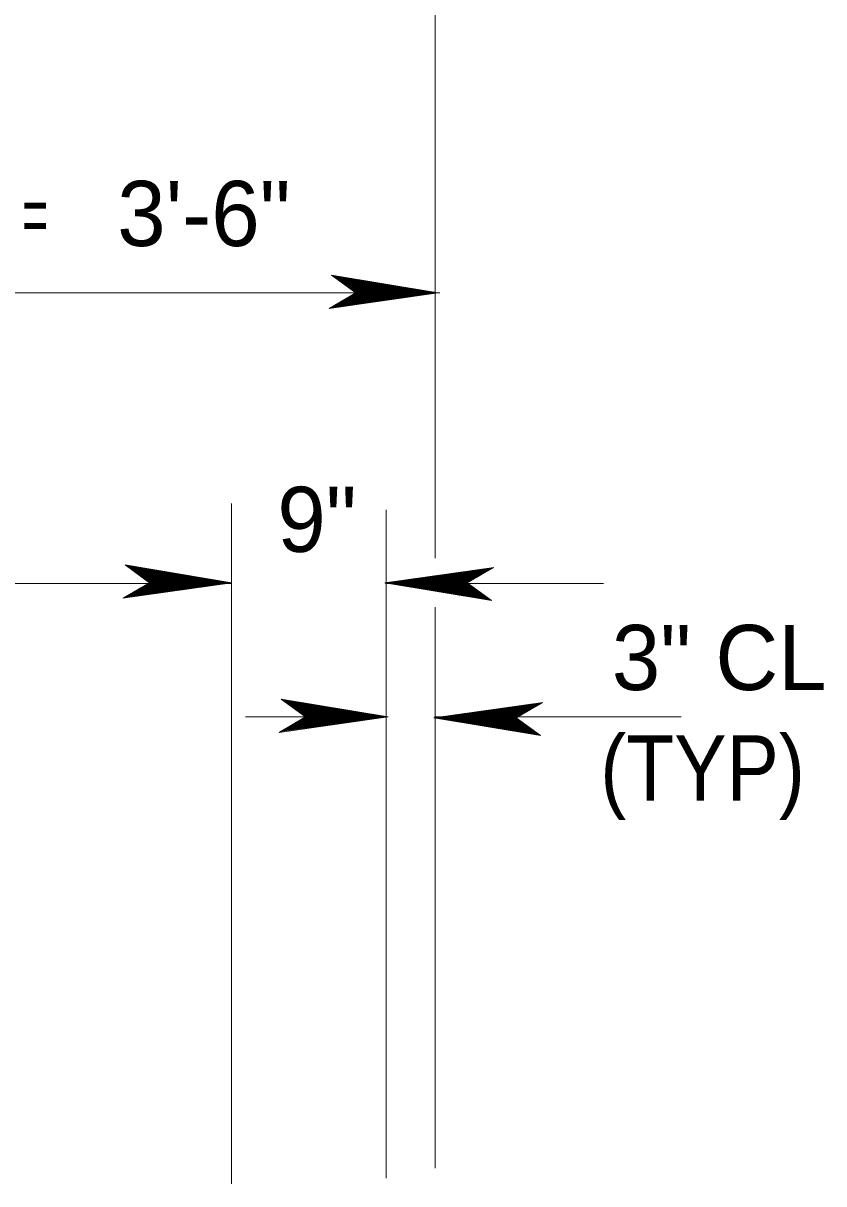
# Model space of a CAD drawing. Extents: x 144 to 252, y 360 to 425.
# Drawn here: x 196.74 to 200.77, y 372.84 to 378.68 of the extents above; entities that cross this region are included whole.
import ezdxf
from ezdxf.enums import TextEntityAlignment as Align

# ---------------------------------------------------------------- set-up
doc = ezdxf.new("R2010")
doc.units = 0
doc.header["$LTSCALE"] = 0.13
for name, color, linetype, lineweight in [('1', 7, 'Continuous', 40), ('16', 7, 'Continuous', 13), ('3', 7, 'Continuous', 13)]:
    doc.layers.add(name, color=color, linetype=linetype, lineweight=lineweight)

msp = doc.modelspace()

# ---------------------------------------------------------------- linework, layer by layer
at = {"layer": '3'}
for p, q in [((198.8108, 375.9887), (198.8108, 379.4017)), ((198.8108, 376.0572), (198.8108, 378.3742)), ((198.8265, 377.3248), (198.2888, 377.4141)), ((198.2888, 377.4141), (198.4113, 377.325)), ((198.8121, 377.3255), (198.2921, 377.4117)), ((198.8012, 377.3255), (198.2953, 377.4094)), ((198.7868, 377.3255), (198.2996, 377.4062)), ((198.7741, 377.3255), (198.3033, 377.4036)), ((198.7627, 377.3255), (198.3067, 377.4012)), ((198.7483, 377.3255), (198.3109, 377.398)), ((198.7356, 377.3255), (198.3147, 377.3952)), ((198.7218, 377.3255), (198.3187, 377.3923)), ((198.708, 377.3255), (198.3228, 377.3893)), ((198.6947, 377.3255), (198.3268, 377.3865)), ((198.6808, 377.3255), (198.3308, 377.3835)), ((198.6683, 377.3255), (198.3346, 377.3808)), ((198.6568, 377.3255), (198.338, 377.3783)), ((198.6412, 377.3255), (198.3426, 377.375)), ((198.6273, 377.3255), (198.3467, 377.372)), ((198.6093, 377.326), (198.3509, 377.3689)), ((198.5954, 377.326), (198.3551, 377.3659)), ((198.5822, 377.326), (198.3589, 377.3631)), ((198.5732, 377.3255), (198.3627, 377.3603)), ((198.5612, 377.3255), (198.3662, 377.3578)), ((198.5473, 377.3255), (198.3703, 377.3547)), ((198.5317, 377.3255), (198.375, 377.3515)), ((198.5191, 377.3255), (198.3787, 377.3487)), ((198.5058, 377.3255), (198.3826, 377.3459)), ((198.4938, 377.3255), (198.3862, 377.3433)), ((198.4793, 377.3255), (198.3904, 377.3402)), ((198.4655, 377.3255), (198.3946, 377.3372)), ((198.4528, 377.3255), (198.3982, 377.3345)), ((198.4396, 377.3255), (198.4022, 377.3317)), ((198.4282, 377.3255), (198.4056, 377.3293)), ((198.8346, 377.3247), (195.3467, 377.3247)), ((198.4113, 377.325), (198.2777, 377.2471)), ((198.2777, 377.2471), (198.8265, 377.3248)), ((198.2837, 377.2506), (198.8121, 377.3255)), ((198.2873, 377.2526), (198.8012, 377.3255)), ((198.2918, 377.2552), (198.7868, 377.3255)), ((198.2959, 377.2577), (198.7741, 377.3255)), ((198.2959, 377.2577), (198.7741, 377.3255)), ((198.2996, 377.2598), (198.7627, 377.3255)), ((198.3042, 377.2625), (198.7483, 377.3255)), ((198.3082, 377.2649), (198.7356, 377.3255)), ((198.3127, 377.2674), (198.7218, 377.3255)), ((198.3171, 377.27), (198.708, 377.3255)), ((198.3213, 377.2725), (198.6947, 377.3255)), ((198.3258, 377.2752), (198.6808, 377.3255)), ((198.3298, 377.2774), (198.6683, 377.3255)), ((198.3336, 377.2797), (198.6568, 377.3255)), ((198.3386, 377.2825), (198.6412, 377.3255)), ((198.343, 377.2852), (198.6273, 377.3255)), ((198.347, 377.2874), (198.6077, 377.3244)), ((198.3502, 377.2893), (198.6093, 377.326)), ((198.3546, 377.2919), (198.5954, 377.326)), ((198.3588, 377.2944), (198.5822, 377.326)), ((198.3603, 377.2953), (198.5732, 377.3255)), ((198.3642, 377.2975), (198.5612, 377.3255)), ((198.3687, 377.3002), (198.5473, 377.3255)), ((198.3737, 377.303), (198.5317, 377.3255)), ((198.3777, 377.3054), (198.5191, 377.3255)), ((198.382, 377.3079), (198.5058, 377.3255)), ((198.3858, 377.3102), (198.4938, 377.3255)), ((198.3905, 377.3128), (198.4793, 377.3255)), ((198.3949, 377.3154), (198.4655, 377.3255)), ((198.399, 377.3177), (198.4528, 377.3255)), ((198.4042, 377.3208), (198.4293, 377.3244)), ((198.4069, 377.3224), (198.4282, 377.3255)), ((198.418, 377.3255), (198.4086, 377.327)), ((198.4111, 377.3248), (198.8265, 377.3248)), ((197.7853, 372.8387), (197.7853, 376.265)), ((198.5633, 372.8667), (198.5633, 376.2329)), ((197.786, 375.8657), (197.2483, 375.955)), ((197.2483, 375.955), (197.3708, 375.8659)), ((197.7716, 375.8664), (197.2516, 375.9527)), ((197.7608, 375.8664), (197.2548, 375.9503)), ((197.7463, 375.8664), (197.2591, 375.9472)), ((197.7336, 375.8664), (197.2628, 375.9445)), ((197.7223, 375.8664), (197.2662, 375.9421)), ((197.7078, 375.8664), (197.2704, 375.9389)), ((197.6951, 375.8664), (197.2742, 375.9362)), ((197.6813, 375.8664), (197.2782, 375.9332)), ((197.6675, 375.8664), (197.2823, 375.9303)), ((197.6542, 375.8664), (197.2862, 375.9274)), ((199.1062, 375.9427), (198.5574, 375.8649)), ((199.1002, 375.9392), (198.5718, 375.8642)), ((199.0967, 375.9372), (198.5827, 375.8642)), ((199.0921, 375.9345), (198.5971, 375.8642)), ((199.088, 375.9321), (198.6098, 375.8642)), ((199.088, 375.9321), (198.6098, 375.8642)), ((199.0843, 375.9299), (198.6212, 375.8642)), ((199.0797, 375.9273), (198.6356, 375.8642)), ((199.0757, 375.9248), (198.6483, 375.8642)), ((198.9726, 375.8648), (199.1062, 375.9427)), ((197.2432, 375.7915), (197.7716, 375.8664)), ((197.2467, 375.7935), (197.7608, 375.8664)), ((197.2513, 375.7962), (197.7463, 375.8664)), ((197.2554, 375.7986), (197.7336, 375.8664)), ((197.2554, 375.7986), (197.7336, 375.8664)), ((197.2591, 375.8007), (197.7223, 375.8664)), ((197.2637, 375.8034), (197.7078, 375.8664)), ((197.2678, 375.8058), (197.6951, 375.8664)), ((197.2722, 375.8083), (197.6813, 375.8664)), ((197.2766, 375.8109), (197.6675, 375.8664)), ((197.2808, 375.8134), (197.6542, 375.8664)), ((197.2853, 375.8161), (197.6403, 375.8664)), ((197.2893, 375.8183), (197.6277, 375.8664)), ((197.6403, 375.8664), (197.2903, 375.9244)), ((197.2931, 375.8206), (197.6163, 375.8664)), ((197.6277, 375.8664), (197.2941, 375.9217)), ((197.6163, 375.8664), (197.2975, 375.9192)), ((197.2981, 375.8234), (197.6007, 375.8664)), ((197.6007, 375.8664), (197.3021, 375.9159)), ((197.3025, 375.8261), (197.5868, 375.8664)), ((197.5868, 375.8664), (197.3062, 375.9129)), ((197.3097, 375.8302), (197.5688, 375.8669)), ((197.5688, 375.8669), (197.3104, 375.9098)), ((197.3141, 375.8328), (197.5549, 375.8669)), ((197.5549, 375.8669), (197.3146, 375.9068)), ((197.3183, 375.8353), (197.5418, 375.8669)), ((197.5418, 375.8669), (197.3184, 375.904)), ((197.3198, 375.8362), (197.5327, 375.8664)), ((197.5327, 375.8664), (197.3222, 375.9013)), ((197.3237, 375.8384), (197.5207, 375.8664)), ((197.5207, 375.8664), (197.3257, 375.8987)), ((197.3282, 375.8411), (197.5068, 375.8664)), ((197.5068, 375.8664), (197.3298, 375.8957)), ((197.3332, 375.8439), (197.4912, 375.8664)), ((197.4912, 375.8664), (197.3345, 375.8924)), ((197.3372, 375.8463), (197.4786, 375.8664)), ((197.4786, 375.8664), (197.3382, 375.8897)), ((197.3415, 375.8488), (197.4653, 375.8664)), ((197.4653, 375.8664), (197.3421, 375.8868)), ((197.3453, 375.8511), (197.4533, 375.8664)), ((197.4533, 375.8664), (197.3457, 375.8842)), ((197.4388, 375.8664), (197.3499, 375.8812)), ((197.35, 375.8537), (197.4388, 375.8664)), ((197.425, 375.8664), (197.3541, 375.8782)), ((197.3544, 375.8563), (197.425, 375.8664)), ((197.4123, 375.8664), (197.3577, 375.8754)), ((197.3585, 375.8587), (197.4123, 375.8664)), ((197.3991, 375.8664), (197.3617, 375.8726)), ((197.3877, 375.8664), (197.3651, 375.8702)), ((197.3664, 375.8633), (197.3877, 375.8664)), ((197.3775, 375.8664), (197.3681, 375.8679)), ((199.0712, 375.9223), (198.6621, 375.8642)), ((199.0668, 375.9197), (198.6759, 375.8642)), ((199.0626, 375.9172), (198.6892, 375.8642)), ((199.0581, 375.9146), (198.7031, 375.8642)), ((199.0541, 375.9123), (198.7157, 375.8642)), ((199.0503, 375.9101), (198.7271, 375.8642)), ((199.0453, 375.9072), (198.7428, 375.8642)), ((199.0409, 375.9046), (198.7566, 375.8642)), ((199.0337, 375.9004), (198.7746, 375.8637)), ((199.0369, 375.9023), (198.7762, 375.8653)), ((199.0293, 375.8978), (198.7885, 375.8637)), ((199.0251, 375.8953), (198.8017, 375.8637)), ((199.0236, 375.8945), (198.8107, 375.8642)), ((199.0197, 375.8922), (198.8227, 375.8642)), ((199.0152, 375.8896), (198.8366, 375.8642)), ((199.0102, 375.8868), (198.8522, 375.8642)), ((199.0062, 375.8843), (198.8648, 375.8642)), ((199.0019, 375.8818), (198.8781, 375.8642)), ((198.9981, 375.8796), (198.8901, 375.8642)), ((198.9934, 375.8769), (198.9046, 375.8642)), ((198.989, 375.8743), (198.9184, 375.8642)), ((198.9849, 375.872), (198.9311, 375.8642)), ((198.9797, 375.8689), (198.9546, 375.8653)), ((198.977, 375.8673), (198.9557, 375.8642)), ((189.8204, 375.8613), (197.7851, 375.8613)), ((189.8204, 375.8613), (197.7802, 375.8613)), ((191.8204, 375.8613), (197.7827, 375.8613)), ((197.3708, 375.8659), (197.2372, 375.788)), ((197.2372, 375.788), (197.786, 375.8657)), ((197.3065, 375.8283), (197.5673, 375.8653)), ((197.3637, 375.8617), (197.3888, 375.8653)), ((197.3706, 375.8657), (197.786, 375.8657)), ((198.5574, 375.8649), (199.0951, 375.7757)), ((198.9728, 375.8649), (198.5574, 375.8649)), ((198.5607, 375.8613), (199.6587, 375.8613)), ((198.5718, 375.8642), (199.0918, 375.778)), ((198.5827, 375.8642), (199.0886, 375.7803)), ((198.5971, 375.8642), (199.0843, 375.7835)), ((198.6098, 375.8642), (199.0806, 375.7862)), ((198.6212, 375.8642), (199.0772, 375.7886)), ((198.6356, 375.8642), (199.073, 375.7917)), ((198.6483, 375.8642), (199.0692, 375.7945)), ((198.6621, 375.8642), (199.0652, 375.7974)), ((198.6759, 375.8642), (199.0611, 375.8004)), ((198.6892, 375.8642), (199.0572, 375.8032)), ((198.7031, 375.8642), (199.0531, 375.8062)), ((198.7157, 375.8642), (199.0493, 375.8089)), ((198.7271, 375.8642), (199.0459, 375.8114)), ((198.7428, 375.8642), (199.0413, 375.8148)), ((198.7566, 375.8642), (199.0373, 375.8177)), ((198.7746, 375.8637), (199.033, 375.8208)), ((198.7885, 375.8637), (199.0288, 375.8238)), ((198.8017, 375.8637), (199.025, 375.8267)), ((198.8107, 375.8642), (199.0212, 375.8294)), ((198.8227, 375.8642), (199.0177, 375.832)), ((198.8366, 375.8642), (199.0136, 375.835)), ((198.8522, 375.8642), (199.0089, 375.8382)), ((198.8648, 375.8642), (199.0052, 375.841)), ((198.8781, 375.8642), (199.0013, 375.8438)), ((198.8901, 375.8642), (198.9977, 375.8465)), ((198.9046, 375.8642), (198.9935, 375.8495)), ((198.9184, 375.8642), (198.9893, 375.8525)), ((198.9311, 375.8642), (198.9857, 375.8553)), ((198.9443, 375.8642), (198.9818, 375.8581)), ((198.9557, 375.8642), (198.9783, 375.8605)), ((198.9659, 375.8642), (198.9753, 375.8628)), ((199.0951, 375.7757), (198.9726, 375.8648)), ((198.8108, 372.9167), (198.8108, 375.742)), ((198.8108, 373.1177), (198.8108, 375.6461)), ((198.5733, 375.1899), (198.0357, 375.2792)), ((198.0357, 375.2792), (198.1582, 375.1901)), ((198.5589, 375.1906), (198.0389, 375.2768)), ((198.5481, 375.1906), (198.0422, 375.2745)), ((198.5337, 375.1906), (198.0464, 375.2713)), ((198.5209, 375.1906), (198.0502, 375.2687)), ((198.5096, 375.1906), (198.0535, 375.2663)), ((198.4952, 375.1906), (198.0577, 375.2631)), ((198.4824, 375.1906), (198.0615, 375.2603)), ((198.4687, 375.1906), (198.0656, 375.2574)), ((198.4548, 375.1906), (198.0697, 375.2544)), ((198.4416, 375.1906), (198.0736, 375.2516)), ((198.4277, 375.1906), (198.0777, 375.2486)), ((198.4151, 375.1906), (198.0814, 375.2459)), ((198.4037, 375.1906), (198.0848, 375.2434)), ((198.388, 375.1906), (198.0894, 375.2401)), ((198.3742, 375.1906), (198.0935, 375.2371)), ((198.3562, 375.1911), (198.0977, 375.234)), ((198.3423, 375.1911), (198.1019, 375.231)), ((198.3291, 375.1911), (198.1058, 375.2282)), ((198.32, 375.1906), (198.1095, 375.2254)), ((199.3533, 375.2625), (198.8046, 375.1848)), ((199.3473, 375.259), (198.819, 375.1841)), ((199.3438, 375.257), (198.8298, 375.1841)), ((199.3392, 375.2543), (198.8442, 375.1841)), ((199.3352, 375.2519), (198.857, 375.1841)), ((199.3352, 375.2519), (198.857, 375.1841)), ((199.3315, 375.2498), (198.8683, 375.1841)), ((199.3269, 375.2471), (198.8827, 375.1841)), ((199.3228, 375.2447), (198.8955, 375.1841)), ((199.3184, 375.2422), (198.9092, 375.1841)), ((199.314, 375.2396), (198.9231, 375.1841)), ((199.3097, 375.2371), (198.9363, 375.1841)), ((199.3053, 375.2344), (198.9502, 375.1841)), ((199.3012, 375.2322), (198.9628, 375.1841)), ((199.2975, 375.2299), (198.9742, 375.1841)), ((199.2925, 375.2271), (198.9899, 375.1841)), ((199.2881, 375.2244), (199.0037, 375.1841)), ((199.2198, 375.1846), (199.3533, 375.2625)), ((197.8547, 375.19), (198.5631, 375.19)), ((198.1582, 375.1901), (198.0246, 375.1122)), ((198.0246, 375.1122), (198.5733, 375.1899)), ((198.0306, 375.1157), (198.5589, 375.1906)), ((198.0341, 375.1177), (198.5481, 375.1906)), ((198.0387, 375.1203), (198.5337, 375.1906)), ((198.0427, 375.1227), (198.5209, 375.1906)), ((198.0427, 375.1227), (198.5209, 375.1906)), ((198.0464, 375.1249), (198.5096, 375.1906)), ((198.051, 375.1276), (198.4952, 375.1906)), ((198.0551, 375.13), (198.4824, 375.1906)), ((198.0595, 375.1325), (198.4687, 375.1906)), ((198.0639, 375.1351), (198.4548, 375.1906)), ((198.0682, 375.1376), (198.4416, 375.1906)), ((198.0727, 375.1402), (198.4277, 375.1906)), ((198.0767, 375.1425), (198.4151, 375.1906)), ((198.0804, 375.1447), (198.4037, 375.1906)), ((198.0854, 375.1476), (198.388, 375.1906)), ((198.0898, 375.1502), (198.3742, 375.1906)), ((198.0938, 375.1525), (198.3546, 375.1895)), ((198.097, 375.1544), (198.3562, 375.1911)), ((198.1014, 375.157), (198.3423, 375.1911)), ((198.1057, 375.1595), (198.3291, 375.1911)), ((198.1072, 375.1603), (198.32, 375.1906)), ((198.1111, 375.1626), (198.308, 375.1906)), ((198.308, 375.1906), (198.1131, 375.2228)), ((198.1155, 375.1653), (198.2942, 375.1906)), ((198.2942, 375.1906), (198.1172, 375.2198)), ((198.1205, 375.1681), (198.2785, 375.1906)), ((198.2785, 375.1906), (198.1218, 375.2166)), ((198.1246, 375.1705), (198.2659, 375.1906)), ((198.2659, 375.1906), (198.1255, 375.2138)), ((198.1288, 375.173), (198.2527, 375.1906)), ((198.2527, 375.1906), (198.1294, 375.211)), ((198.1327, 375.1753), (198.2407, 375.1906)), ((198.2407, 375.1906), (198.133, 375.2083)), ((198.2262, 375.1906), (198.1372, 375.2053)), ((198.1373, 375.1779), (198.2262, 375.1906)), ((198.2123, 375.1906), (198.1414, 375.2023)), ((198.1418, 375.1805), (198.2123, 375.1906)), ((198.1997, 375.1906), (198.1451, 375.1996)), ((198.1458, 375.1828), (198.1997, 375.1906)), ((198.1864, 375.1906), (198.149, 375.1968)), ((198.1511, 375.1859), (198.1762, 375.1895)), ((198.175, 375.1906), (198.1524, 375.1943)), ((198.1538, 375.1875), (198.175, 375.1906)), ((198.1648, 375.1906), (198.1554, 375.1921)), ((198.1579, 375.1899), (198.5733, 375.1899)), ((198.8046, 375.1848), (199.3423, 375.0955)), ((199.22, 375.1848), (198.8046, 375.1848)), ((198.808, 375.19), (200.0502, 375.19)), ((198.819, 375.1841), (199.339, 375.0978)), ((198.8298, 375.1841), (199.3357, 375.1002)), ((198.8442, 375.1841), (199.3315, 375.1033)), ((198.857, 375.1841), (199.3277, 375.106)), ((198.8683, 375.1841), (199.3244, 375.1084)), ((198.8827, 375.1841), (199.3202, 375.1116)), ((198.8955, 375.1841), (199.3164, 375.1143)), ((198.9092, 375.1841), (199.3123, 375.1173)), ((198.9231, 375.1841), (199.3082, 375.1202)), ((198.9363, 375.1841), (199.3043, 375.1231)), ((198.9502, 375.1841), (199.3003, 375.1261)), ((198.9628, 375.1841), (199.2965, 375.1287)), ((198.9742, 375.1841), (199.2931, 375.1312)), ((198.9899, 375.1841), (199.2885, 375.1346)), ((199.0037, 375.1841), (199.2844, 375.1376)), ((199.2809, 375.2202), (199.0217, 375.1836)), ((199.0217, 375.1836), (199.2802, 375.1407)), ((199.2841, 375.2222), (199.0233, 375.1852)), ((199.2765, 375.2177), (199.0357, 375.1836)), ((199.0357, 375.1836), (199.276, 375.1437)), ((199.2722, 375.2152), (199.0488, 375.1836)), ((199.0488, 375.1836), (199.2722, 375.1465)), ((199.2707, 375.2143), (199.0579, 375.1841)), ((199.0579, 375.1841), (199.2684, 375.1492)), ((199.2668, 375.2121), (199.0699, 375.1841)), ((199.0699, 375.1841), (199.2648, 375.1518)), ((199.2624, 375.2094), (199.0837, 375.1841)), ((199.0837, 375.1841), (199.2608, 375.1548)), ((199.2574, 375.2066), (199.0994, 375.1841)), ((199.0994, 375.1841), (199.2561, 375.1581)), ((199.2533, 375.2042), (199.112, 375.1841)), ((199.112, 375.1841), (199.2524, 375.1608)), ((199.2491, 375.2017), (199.1252, 375.1841)), ((199.1252, 375.1841), (199.2485, 375.1637)), ((199.2452, 375.1994), (199.1372, 375.1841)), ((199.1372, 375.1841), (199.2449, 375.1663)), ((199.2406, 375.1968), (199.1517, 375.1841)), ((199.1517, 375.1841), (199.2407, 375.1693)), ((199.2362, 375.1942), (199.1656, 375.1841)), ((199.1656, 375.1841), (199.2365, 375.1723)), ((199.2321, 375.1918), (199.1782, 375.1841)), ((199.1782, 375.1841), (199.2328, 375.1751)), ((199.1915, 375.1841), (199.2289, 375.1779)), ((199.2268, 375.1887), (199.2018, 375.1852)), ((199.2242, 375.1872), (199.2029, 375.1841)), ((199.2029, 375.1841), (199.2255, 375.1803)), ((199.2131, 375.1841), (199.2225, 375.1826)), ((199.3423, 375.0955), (199.2198, 375.1846)), ((198.8108, 373.1177), (198.8108, 373.7005))]:
    msp.add_line(p, q, dxfattribs=at)

# ---------------------------------------------------------------- texts
at = {"layer": '1', "width": 0.6}
msp.add_text('=', height=0.2833, dxfattribs=at).set_placement((196.7957, 377.5776), align=Align.CENTER)
at = {"layer": '16'}
msp.add_text('3\'-6"', height=0.3281, dxfattribs=at).set_placement((197.6459, 377.5612), align=Align.CENTER)
for s, p in [('9"', (198.0157, 376.0207)), ('3" CL', (199.7011, 375.325))]:
    msp.add_text(s, height=0.3281, dxfattribs=at).set_placement(p)
at = {"layer": '16', "width": 0.9}
msp.add_text('(TYP)', height=0.3281, dxfattribs=at).set_placement((199.6428, 374.7688))

doc.saveas('drawing.dxf')
